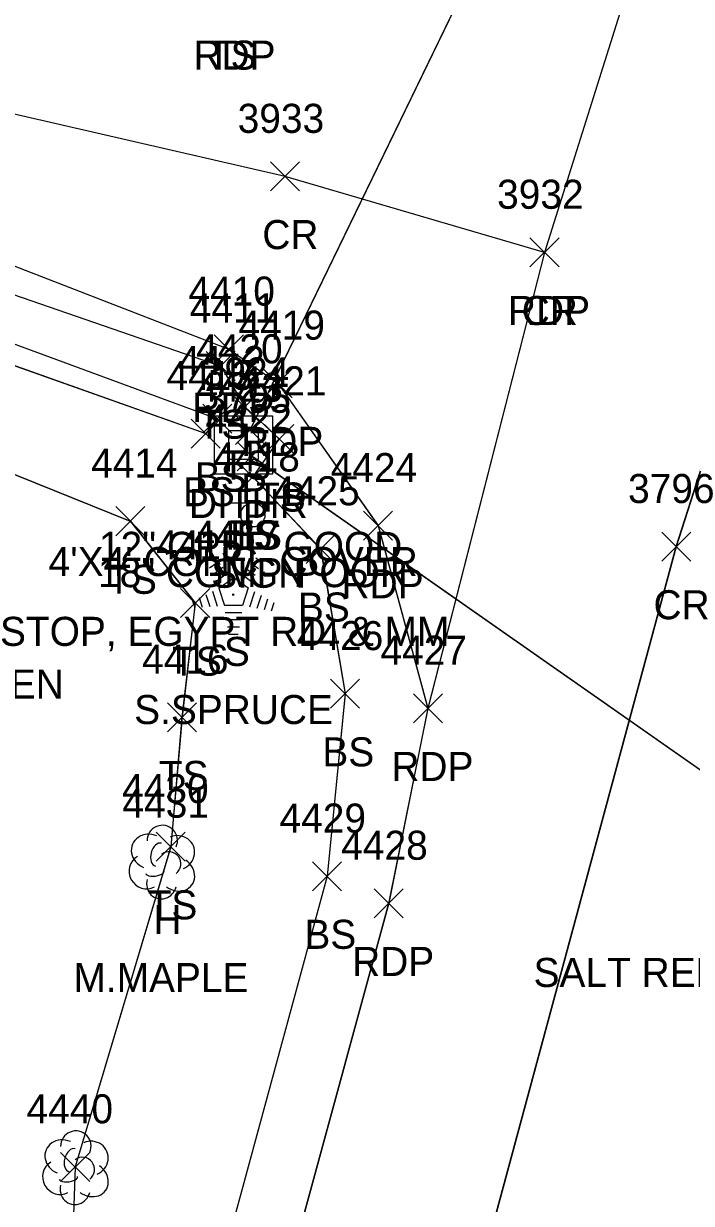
# Model space of a CAD drawing. Extents: x 1554668 to 1563881, y 831386 to 834374.
# Drawn here: x 1562471.8 to 1562517.8, y 833993 to 834074.2 of the extents above; entities that cross this region are included whole.
import ezdxf

# ---------------------------------------------------------------- set-up
doc = ezdxf.new("R2010")
doc.units = 0
for name, color, linetype in [('D_A', 7, 'Continuous'), ('D_C', 7, 'Continuous'), ('D_I', 7, 'Continuous'), ('D_TIC', 7, 'Continuous'), ('DCP', 7, 'Continuous'), ('DS', 7, 'Continuous'), ('L_A', 7, 'Continuous'), ('L_C', 7, 'Continuous'), ('L_I', 7, 'Continuous'), ('L_TIC', 7, 'Continuous'), ('LELB', 7, 'Continuous'), ('LTC', 7, 'Continuous'), ('LTD', 7, 'Continuous'), ('P_A', 7, 'Continuous'), ('P_I', 7, 'Continuous'), ('P_TIC', 7, 'Continuous'), ('PET', 7, 'Continuous'), ('PRC', 7, 'Continuous'), ('S_A', 7, 'Continuous'), ('S_C', 7, 'Continuous'), ('S_I', 7, 'Continuous'), ('SSGN', 7, 'Continuous')]:
    doc.layers.add(name, color=color, linetype=linetype)

msp = doc.modelspace()

# ---------------------------------------------------------------- linework, layer by layer
at = {"layer": 'D_TIC'}
for points in [[(1562486.419, 834045.242), (1562488.419, 834047.242)], [(1562488.419, 834045.242), (1562486.419, 834047.242)], [(1562486.529, 834043.432), (1562488.529, 834045.432)], [(1562488.529, 834043.432), (1562486.529, 834045.432)]]:
    msp.add_lwpolyline(points, dxfattribs=at)
at = {"layer": 'DCP'}
for points in [[(1562487.419, 834046.242), (1562533.892, 834142.054)], [(1562487.423, 834046.249), (1562533.895, 834142.059)], [(1562487.423, 834046.249), (1562533.895, 834142.059)], [(1562487.423, 834046.249), (1562533.895, 834142.059)], [(1562543.528, 834005.24), (1562487.529, 834044.432)], [(1562543.531, 834005.244), (1562487.533, 834044.441)], [(1562543.531, 834005.244), (1562487.533, 834044.441)], [(1562543.531, 834005.244), (1562487.533, 834044.441)]]:
    msp.add_lwpolyline(points, dxfattribs=at)
at = {"layer": 'DS'}
for p, q in [((1562484.96, 834047.215), (1562488.96, 834047.215)), ((1562484.96, 834043.215), (1562484.971, 834047.215)), ((1562488.96, 834047.215), (1562488.96, 834043.215)), ((1562485.96, 834046.215), (1562487.96, 834046.215)), ((1562485.96, 834044.215), (1562485.96, 834046.215)), ((1562487.96, 834046.215), (1562487.96, 834044.215)), ((1562486.963, 834045.225), (1562486.963, 834045.225)), ((1562487.96, 834044.215), (1562485.96, 834044.215)), ((1562488.96, 834043.215), (1562484.96, 834043.215)), ((1562487.46, 834043.215), (1562487.96, 834043.215))]:
    msp.add_line(p, q, dxfattribs=at)
at = {"layer": 'L_TIC'}
for points in [[(1562484.392, 834049.646), (1562486.392, 834051.646)], [(1562486.392, 834049.646), (1562484.392, 834051.646)], [(1562486.046, 834046.838), (1562488.046, 834048.838)], [(1562488.046, 834046.838), (1562486.046, 834048.838)], [(1562484.164, 834046.024), (1562486.164, 834048.024)], [(1562486.164, 834046.024), (1562484.164, 834048.024)], [(1562483.357, 834045), (1562485.357, 834047)], [(1562485.357, 834045), (1562483.357, 834047)], [(1562483.357, 834045), (1562485.357, 834047)], [(1562485.357, 834045), (1562483.357, 834047)], [(1562488.41, 834044.633), (1562490.41, 834046.633)], [(1562490.41, 834044.633), (1562488.41, 834046.633)], [(1562486.603, 834042.022), (1562488.603, 834044.022)], [(1562488.603, 834042.022), (1562486.603, 834044.022)], [(1562486.603, 834042.022), (1562488.603, 834044.022)], [(1562488.603, 834042.022), (1562486.603, 834044.022)], [(1562478.172, 834038.973), (1562480.172, 834040.973)], [(1562480.172, 834038.973), (1562478.172, 834040.973)], [(1562491.263, 834037.064), (1562493.263, 834039.064)], [(1562493.263, 834037.064), (1562491.263, 834039.064)], [(1562482.634, 834033.339), (1562484.634, 834035.339)], [(1562484.634, 834033.339), (1562482.634, 834035.339)], [(1562492.941, 834027.098), (1562494.941, 834029.098)], [(1562494.941, 834027.098), (1562492.941, 834029.098)], [(1562481.728, 834025.474), (1562483.728, 834027.474)], [(1562483.728, 834025.474), (1562481.728, 834027.474)], [(1562480.956, 834016.568), (1562482.956, 834018.568)], [(1562482.956, 834016.568), (1562480.956, 834018.568)], [(1562491.705, 834014.54), (1562493.705, 834016.54)], [(1562493.705, 834014.54), (1562491.705, 834016.54)], [(1562474.382, 833994.53), (1562476.382, 833996.53)], [(1562476.382, 833994.53), (1562474.382, 833996.53)]]:
    msp.add_lwpolyline(points, dxfattribs=at)
at = {"layer": 'LELB'}
for points in [[(1562443.369, 834064.364), (1562440.27, 834060.126), (1562440.179, 834056.769), (1562462.161, 834046.825), (1562479.172, 834039.973), (1562483.634, 834034.339), (1562482.728, 834026.474), (1562481.956, 834017.568), (1562475.382, 833995.53), (1562474.907, 833981.597), (1562477.796, 833971.146), (1562474.671, 833958.863), (1562474.695, 833956.52), (1562476.835, 833955.638), (1562466.528, 833927.959), (1562464.896, 833923.683), (1562456.361, 833893.869), (1562447.843, 833876.92), (1562444.919, 833863.488)], [(1562443.372, 834064.371), (1562440.278, 834060.128), (1562440.185, 834056.774), (1562462.168, 834046.828), (1562479.179, 834039.977), (1562483.64, 834034.343), (1562482.736, 834026.476), (1562481.962, 834017.573), (1562475.384, 833995.54), (1562474.909, 833981.607), (1562477.799, 833971.154), (1562474.676, 833958.869), (1562474.7, 833956.527), (1562476.834, 833955.648), (1562466.529, 833927.967), (1562464.895, 833923.691), (1562456.363, 833893.876), (1562447.847, 833876.928), (1562444.925, 833863.497)], [(1562443.372, 834064.371), (1562440.278, 834060.128), (1562440.185, 834056.774), (1562462.168, 834046.828), (1562479.179, 834039.977), (1562483.64, 834034.343), (1562482.736, 834026.476), (1562481.962, 834017.573), (1562475.384, 833995.54), (1562474.909, 833981.607), (1562477.799, 833971.154), (1562474.676, 833958.869), (1562474.7, 833956.527), (1562476.834, 833955.648), (1562466.529, 833927.967), (1562464.895, 833923.691), (1562456.363, 833893.876), (1562447.847, 833876.928), (1562444.925, 833863.497)], [(1562443.372, 834064.371), (1562440.278, 834060.128), (1562440.185, 834056.774), (1562462.168, 834046.828), (1562479.179, 834039.977), (1562483.64, 834034.343), (1562482.736, 834026.476), (1562481.962, 834017.573), (1562475.384, 833995.54), (1562474.909, 833981.607), (1562477.799, 833971.154), (1562474.676, 833958.869), (1562474.7, 833956.527), (1562476.834, 833955.648), (1562466.529, 833927.967), (1562464.895, 833923.691), (1562456.363, 833893.876), (1562447.847, 833876.928), (1562444.925, 833863.497)], [(1562443.369, 834064.364), (1562466.074, 834057.315), (1562485.392, 834050.646), (1562487.046, 834047.838), (1562489.41, 834045.633), (1562487.603, 834043.022)], [(1562443.372, 834064.371), (1562466.08, 834057.319), (1562485.395, 834050.652), (1562487.05, 834047.844), (1562489.419, 834045.636), (1562487.608, 834043.027)], [(1562443.372, 834064.371), (1562466.08, 834057.319), (1562485.395, 834050.652), (1562487.05, 834047.844), (1562489.419, 834045.636), (1562487.608, 834043.027)], [(1562443.372, 834064.371), (1562466.08, 834057.319), (1562485.395, 834050.652), (1562487.05, 834047.844), (1562489.419, 834045.636), (1562487.608, 834043.027)], [(1562444.493, 834063.001), (1562443.667, 834060.94), (1562464.494, 834053.056), (1562484.357, 834046)], [(1562444.503, 834063.002), (1562443.675, 834060.942), (1562464.497, 834053.062), (1562484.363, 834046.005)], [(1562444.503, 834063.002), (1562443.675, 834060.942), (1562464.497, 834053.062), (1562484.363, 834046.005)], [(1562444.503, 834063.002), (1562443.675, 834060.942), (1562464.497, 834053.062), (1562484.363, 834046.005)], [(1562444.493, 834063.001), (1562464.916, 834054.471), (1562485.164, 834047.024), (1562484.357, 834046)], [(1562444.503, 834063.002), (1562464.924, 834054.474), (1562485.17, 834047.028), (1562484.363, 834046.005)], [(1562444.503, 834063.002), (1562464.924, 834054.474), (1562485.17, 834047.028), (1562484.363, 834046.005)], [(1562444.503, 834063.002), (1562464.924, 834054.474), (1562485.17, 834047.028), (1562484.363, 834046.005)], [(1562487.603, 834043.022), (1562492.263, 834038.064), (1562493.941, 834028.098), (1562492.705, 834015.54), (1562484.92, 833986.839), (1562486.563, 833985.393), (1562478.149, 833957.136), (1562476.214, 833958.05)], [(1562487.608, 834043.027), (1562492.269, 834038.068), (1562493.945, 834028.104), (1562492.707, 834015.549), (1562484.921, 833986.85), (1562486.566, 833985.401), (1562478.156, 833957.142), (1562476.216, 833958.059)], [(1562487.608, 834043.027), (1562492.269, 834038.068), (1562493.945, 834028.104), (1562492.707, 834015.549), (1562484.921, 833986.85), (1562486.566, 833985.401), (1562478.156, 833957.142), (1562476.216, 833958.059)], [(1562487.608, 834043.027), (1562492.269, 834038.068), (1562493.945, 834028.104), (1562492.707, 834015.549), (1562484.921, 833986.85), (1562486.566, 833985.401), (1562478.156, 833957.142), (1562476.216, 833958.059)]]:
    msp.add_lwpolyline(points, dxfattribs=at)
at = {"layer": 'LTC'}
for p, q in [((1562484.419, 834037.218), (1562484.774, 834037.476)), ((1562487.818, 834037.459), (1562488.237, 834037.154)), ((1562484.629, 834036.753), (1562485.158, 834037.137)), ((1562484.838, 834036.287), (1562485.542, 834036.798)), ((1562487.076, 834036.762), (1562487.755, 834036.268)), ((1562487.446, 834037.11), (1562487.996, 834036.711)), ((1562485.048, 834035.821), (1562485.926, 834036.459)), ((1562485.273, 834035.366), (1562486.284, 834036.101)), ((1562486.284, 834036.101), (1562487.281, 834035.376)), ((1562486.704, 834036.414), (1562487.514, 834035.825)), ((1562484.818, 834035.147), (1562485.149, 834034.128)), ((1562485.273, 834035.366), (1562485.66, 834034.173)), ((1562487.281, 834035.376), (1562486.89, 834034.173)), ((1562487.719, 834035.105), (1562487.381, 834034.065)), ((1562483.452, 834034.497), (1562483.604, 834034.03)), ((1562483.907, 834034.714), (1562484.119, 834034.062)), ((1562484.363, 834034.931), (1562484.634, 834034.095)), ((1562486.89, 834034.173), (1562485.66, 834034.173)), ((1562488.163, 834034.855), (1562487.876, 834033.97)), ((1562488.608, 834034.605), (1562488.371, 834033.875)), ((1562489.052, 834034.354), (1562488.866, 834033.78)), ((1562486.852, 834033.673), (1562485.707, 834033.673)), ((1562486.768, 834033.173), (1562485.78, 834033.173)), ((1562486.684, 834032.673), (1562485.853, 834032.673)), ((1562486.601, 834032.173), (1562485.926, 834032.173))]:
    msp.add_line(p, q, dxfattribs=at)
at = {"layer": 'LTD'}
for p, q in [((1562481.326, 834016.562), (1562481.326, 834016.562)), ((1562481.326, 834016.562), (1562481.326, 834016.562)), ((1562475.382, 833995.53), (1562475.382, 833995.53)), ((1562475.382, 833995.53), (1562475.382, 833995.53))]:
    msp.add_line(p, q, dxfattribs=at)
for centre in [(1562481.373, 834017.996), (1562475.429, 833996.964)]:
    msp.add_arc(centre, 1.047, 335.52715, 180.95627, dxfattribs=at)
for centre, major_axis, ratio, start_param, end_param in [((1562480.534, 834017.229), (1.21, -0.512), 0.895232, 1.570796, 4.712389), ((1562482.368, 834017.146), (-1.141, -0.483), 0.949671, 1.570796, 4.712389), ((1562481.118, 834017.021), (-0.208, -0.792), 0.645439, 3.141593, 6.283185), ((1562481.826, 834016.396), (-0.5, 0.667), 0.989748, 3.141593, 6.283185), ((1562480.243, 834015.854), (0.584, -1.042), 0.959034, 3.141593, 6.283185), ((1562482.326, 834015.729), (-1.09, 0.792), 0.841452, 1.570796, 4.712389), ((1562480.868, 834015.812), (-0.625, -0.083), 0.423636, 0, 3.141593), ((1562481.326, 834015.062), (0.265, 1.061), 0.942809, 1.570796, 4.712389), ((1562474.59, 833996.197), (1.21, -0.512), 0.895232, 1.570796, 4.712389), ((1562475.174, 833995.989), (-0.208, -0.792), 0.645439, 3.141593, 6.283185), ((1562476.424, 833996.114), (-1.141, -0.483), 0.949671, 1.570796, 4.712389), ((1562475.882, 833995.364), (-0.5, 0.667), 0.989748, 3.141593, 6.283185), ((1562474.299, 833994.822), (0.584, -1.042), 0.959034, 3.141593, 6.283185), ((1562476.382, 833994.697), (-1.09, 0.792), 0.841452, 1.570796, 4.712389), ((1562474.924, 833994.78), (-0.625, -0.083), 0.423636, 0, 3.141593), ((1562475.382, 833994.03), (0.265, 1.061), 0.942809, 1.570796, 4.712389)]:
    msp.add_ellipse(centre, major_axis=major_axis, ratio=ratio, start_param=start_param, end_param=end_param, dxfattribs=at)
at = {"layer": 'P_TIC'}
for points in [[(1562488.819, 834062.697), (1562490.819, 834064.697)], [(1562490.819, 834062.697), (1562488.819, 834064.697)], [(1562506.663, 834057.473), (1562508.663, 834059.473)], [(1562508.663, 834057.473), (1562506.663, 834059.473)], [(1562506.663, 834057.473), (1562508.663, 834059.473)], [(1562508.663, 834057.473), (1562506.663, 834059.473)], [(1562484.949, 834050.808), (1562486.949, 834052.808)], [(1562486.949, 834050.808), (1562484.949, 834052.808)], [(1562488.315, 834048.467), (1562490.315, 834050.467)], [(1562490.315, 834048.467), (1562488.315, 834050.467)], [(1562495.216, 834038.663), (1562497.216, 834040.663)], [(1562497.216, 834038.663), (1562495.216, 834040.663)], [(1562515.728, 834037.221), (1562517.728, 834039.221)], [(1562517.728, 834037.221), (1562515.728, 834039.221)], [(1562498.641, 834026.091), (1562500.641, 834028.091)], [(1562500.641, 834026.091), (1562498.641, 834028.091)], [(1562498.641, 834026.091), (1562500.641, 834028.091)], [(1562500.641, 834026.091), (1562498.641, 834028.091)], [(1562495.942, 834012.671), (1562497.942, 834014.671)], [(1562497.942, 834012.671), (1562495.942, 834014.671)]]:
    msp.add_lwpolyline(points, dxfattribs=at)
at = {"layer": 'PET'}
for points in [[(1562517.255, 834088.953), (1562507.663, 834058.473), (1562499.641, 834027.091)], [(1562517.258, 834088.963), (1562507.673, 834058.475), (1562499.647, 834027.095)], [(1562517.258, 834088.963), (1562507.673, 834058.475), (1562499.647, 834027.095)], [(1562517.258, 834088.963), (1562507.673, 834058.475), (1562499.647, 834027.095)], [(1562435.459, 834067.179), (1562467.01, 834059.144), (1562485.949, 834051.808), (1562489.315, 834049.467), (1562496.216, 834039.663), (1562499.641, 834027.091), (1562496.942, 834013.671), (1562484.997, 833969.829), (1562474.119, 833928.894), (1562465.329, 833892.835), (1562453.027, 833838.818), (1562446.513, 833813.556), (1562435.697, 833762.843)], [(1562435.465, 834067.183), (1562467.015, 834059.149), (1562485.955, 834051.812), (1562489.324, 834049.47), (1562496.226, 834039.666), (1562499.647, 834027.095), (1562496.946, 834013.679), (1562485.004, 833969.835), (1562474.119, 833928.902), (1562465.328, 833892.841), (1562453.028, 833838.829), (1562446.514, 833813.563), (1562435.7, 833762.854)], [(1562435.465, 834067.183), (1562467.015, 834059.149), (1562485.955, 834051.812), (1562489.324, 834049.47), (1562496.226, 834039.666), (1562499.647, 834027.095), (1562496.946, 834013.679), (1562485.004, 833969.835), (1562474.119, 833928.902), (1562465.328, 833892.841), (1562453.028, 833838.829), (1562446.514, 833813.563), (1562435.7, 833762.854)], [(1562435.465, 834067.183), (1562467.015, 834059.149), (1562485.955, 834051.812), (1562489.324, 834049.47), (1562496.226, 834039.666), (1562499.647, 834027.095), (1562496.946, 834013.679), (1562485.004, 833969.835), (1562474.119, 833928.902), (1562465.328, 833892.841), (1562453.028, 833838.829), (1562446.514, 833813.563), (1562435.7, 833762.854)]]:
    msp.add_lwpolyline(points, dxfattribs=at)
at = {"layer": 'PRC'}
for points in [[(1562507.663, 834058.473), (1562489.819, 834063.697), (1562466.193, 834069.126), (1562436.129, 834075.748), (1562408.218, 834079.724), (1562320.462, 834097.246), (1562291.247, 834107.325), (1562261.719, 834117.67), (1562206.924, 834138.361), (1562180.714, 834150.238), (1562141.773, 834168.724), (1562097.331, 834192.804), (1562041.495, 834228.278), (1562010.592, 834247.192), (1561969.731, 834271.926), (1561947.65, 834288.488), (1561929.769, 834303.06), (1561897.798, 834328.164), (1561868.944, 834345.787)], [(1562507.673, 834058.475), (1562489.821, 834063.703), (1562466.195, 834069.132), (1562436.136, 834075.752), (1562408.228, 834079.731), (1562320.469, 834097.25), (1562291.251, 834107.331), (1562261.726, 834117.669), (1562206.928, 834138.365), (1562180.725, 834150.241), (1562141.776, 834168.728), (1562097.334, 834192.81), (1562041.498, 834228.283), (1562010.595, 834247.198), (1561969.736, 834271.928), (1561947.66, 834288.488), (1561929.776, 834303.061), (1561897.805, 834328.165), (1561868.953, 834345.787)], [(1562507.673, 834058.475), (1562489.821, 834063.703), (1562466.195, 834069.132), (1562436.136, 834075.752), (1562408.228, 834079.731), (1562320.469, 834097.25), (1562291.251, 834107.331), (1562261.726, 834117.669), (1562206.928, 834138.365), (1562180.725, 834150.241), (1562141.776, 834168.728), (1562097.334, 834192.81), (1562041.498, 834228.283), (1562010.595, 834247.198), (1561969.736, 834271.928), (1561947.66, 834288.488), (1561929.776, 834303.061), (1561897.805, 834328.165), (1561868.953, 834345.787)], [(1562507.673, 834058.475), (1562489.821, 834063.703), (1562466.195, 834069.132), (1562436.136, 834075.752), (1562408.228, 834079.731), (1562320.469, 834097.25), (1562291.251, 834107.331), (1562261.726, 834117.669), (1562206.928, 834138.365), (1562180.725, 834150.241), (1562141.776, 834168.728), (1562097.334, 834192.81), (1562041.498, 834228.283), (1562010.595, 834247.198), (1561969.736, 834271.928), (1561947.66, 834288.488), (1561929.776, 834303.061), (1561897.805, 834328.165), (1561868.953, 834345.787)], [(1562374.328, 833358.788), (1562379.819, 833391.645), (1562386.805, 833432.043), (1562394.132, 833473.552), (1562401.52, 833515.146), (1562408.626, 833554.57), (1562418.317, 833607.158), (1562425.122, 833644.153), (1562437.129, 833703.517), (1562446.816, 833750.468), (1562457.117, 833798.654), (1562467.75, 833845.524), (1562476.843, 833883.646), (1562492.325, 833945.243), (1562502.519, 833985.558), (1562516.732, 834038.229), (1562535.447, 834096.625), (1562549.682, 834139.255), (1562553.417, 834150.261)], [(1562374.328, 833358.788), (1562379.819, 833391.645), (1562386.805, 833432.043), (1562394.132, 833473.552), (1562401.52, 833515.146), (1562408.626, 833554.57), (1562418.317, 833607.158), (1562425.122, 833644.153), (1562437.129, 833703.517), (1562446.816, 833750.468), (1562457.117, 833798.654), (1562467.75, 833845.524), (1562476.843, 833883.646), (1562492.325, 833945.243), (1562502.519, 833985.558), (1562516.732, 834038.229), (1562535.447, 834096.625), (1562549.682, 834139.255), (1562553.417, 834150.261)], [(1562374.328, 833358.788), (1562379.819, 833391.645), (1562386.805, 833432.043), (1562394.132, 833473.552), (1562401.52, 833515.146), (1562408.626, 833554.57), (1562418.317, 833607.158), (1562425.122, 833644.153), (1562437.129, 833703.517), (1562446.816, 833750.468), (1562457.117, 833798.654), (1562467.75, 833845.524), (1562476.843, 833883.646), (1562492.325, 833945.243), (1562502.519, 833985.558), (1562516.732, 834038.229), (1562535.447, 834096.625), (1562549.682, 834139.255), (1562553.417, 834150.261)], [(1562374.328, 833358.78), (1562379.82, 833391.635), (1562386.804, 833432.041), (1562394.133, 833473.548), (1562401.522, 833515.144), (1562408.625, 833554.563), (1562418.32, 833607.155), (1562425.125, 833644.147), (1562437.128, 833703.511), (1562446.815, 833750.458), (1562457.117, 833798.648), (1562467.753, 833845.523), (1562476.843, 833883.643), (1562492.321, 833945.235), (1562502.515, 833985.553), (1562516.728, 834038.221), (1562535.444, 834096.612), (1562549.678, 834139.252), (1562553.413, 834150.251)]]:
    msp.add_lwpolyline(points, dxfattribs=at)
at = {"layer": 'SSGN'}
for p, q in [((1562485.953, 834041.243), (1562489.287, 834041.243)), ((1562487.6, 834040.41), (1562487.6, 834040.41))]:
    msp.add_line(p, q, dxfattribs=at)
msp.add_circle((1562487.6, 834040.41), 0.833, dxfattribs=at)

# ---------------------------------------------------------------- texts
at = {"layer": 'D_A'}
for s, p in [('P', (1562486.797, 834041.242)), ('DITHR', (1562483.207, 834040.194)), ('P', (1562486.907, 834039.432))]:
    msp.add_text(s, height=2, dxfattribs=at).set_placement(p)
at = {"layer": 'D_C'}
for s, p in [('12" CPEP GOOD', (1562477.017, 834037.242)), ("4'X4' CONC. COVER", (1562473.553, 834036.194)), ('18" CGMP POOR', (1562476.955, 834035.432))]:
    msp.add_text(s, height=2, dxfattribs=at).set_placement(p)
at = {"layer": 'D_I'}
for s, p in [('3924', (1562484.159, 834049.242)), ('4423', (1562483.719, 834048.194)), ('3795', (1562484.27, 834047.432))]:
    msp.add_text(s, height=2, dxfattribs=at).set_placement(p)
at = {"layer": 'L_A'}
for s, p in [('TS', (1562484.439, 834071.048)), ('TS', (1562483.801, 834045.646)), ('TS', (1562485.456, 834042.838)), ('BS', (1562483.605, 834042.024)), ('BS', (1562482.798, 834041)), ('BS', (1562482.798, 834041)), ('TS', (1562487.819, 834040.633)), ('TS', (1562486.012, 834038.022)), ('BS', (1562486.044, 834038.022)), ('TS', (1562477.581, 834034.973)), ('BS', (1562490.704, 834033.064)), ('S', (1562485.61, 834030.01)), ('TS', (1562482.043, 834029.339)), ('GARDEN', (1562463.155, 834027.765)), ('BS', (1562492.382, 834023.098)), ('TS', (1562481.137, 834021.474)), ('TS', (1562480.366, 834012.568)), ('H', (1562480.759, 834011.562)), ('BS', (1562491.146, 834010.54))]:
    msp.add_text(s, height=2, dxfattribs=at).set_placement(p)
at = {"layer": 'L_C'}
for s, p in [('S.SPRUCE', (1562479.437, 834026.01)), ('M.MAPLE', (1562475.263, 834007.562))]:
    msp.add_text(s, height=2, dxfattribs=at).set_placement(p)
at = {"layer": 'L_I'}
for s, p in [('4411', (1562483.266, 834053.646)), ('4420', (1562483.7, 834050.838)), ('4412', (1562482.471, 834050.024)), ('4413', (1562481.664, 834049)), ('4413', (1562481.664, 834049)), ('4421', (1562486.717, 834048.633)), ('4422', (1562484.343, 834046.022)), ('4422', (1562484.343, 834046.022)), ('4414', (1562476.479, 834042.973)), ('4425', (1562489.003, 834041.064)), ('4417', (1562483.531, 834038.01)), ('4415', (1562480.941, 834037.339)), ('4426', (1562490.626, 834031.098)), ('4416', (1562479.98, 834029.474)), ('4430', (1562478.61, 834020.568)), ('4431', (1562478.633, 834019.562)), ('4429', (1562489.437, 834018.54)), ('4440', (1562472.036, 833998.53)), ('4440', (1562472.036, 833998.53))]:
    msp.add_text(s, height=2, dxfattribs=at).set_placement(p)
at = {"layer": 'LTC'}
msp.add_text('.', height=1.037, rotation=270, dxfattribs=at).set_placement((1562486.167, 834035.114))
at = {"layer": 'P_A'}
for s, p in [('RDP', (1562483.518, 834071.048)), ('CR', (1562488.252, 834058.697)), ('RDP', (1562505.151, 834053.473)), ('CR', (1562506.096, 834053.473)), ('RDP', (1562483.437, 834046.808)), ('RDP', (1562486.803, 834044.467)), ('RDP', (1562493.704, 834034.663)), ('CR', (1562515.161, 834033.221)), ('RDP', (1562497.129, 834022.091)), ('RDP', (1562497.129, 834022.091)), ('RDP', (1562494.431, 834008.671))]:
    msp.add_text(s, height=2, dxfattribs=at).set_placement(p)
at = {"layer": 'P_I'}
for s, p in [('3933', (1562486.559, 834066.697)), ('3932', (1562504.403, 834061.473)), ('3932', (1562504.403, 834061.473)), ('4410', (1562483.169, 834054.808)), ('4419', (1562486.614, 834052.467)), ('4424', (1562492.956, 834042.663)), ('3796', (1562513.413, 834041.221)), ('4427', (1562496.381, 834030.091)), ('4427', (1562496.381, 834030.091)), ('4428', (1562493.683, 834016.671))]:
    msp.add_text(s, height=2, dxfattribs=at).set_placement(p)
at = {"layer": 'S_A'}
msp.add_text('SIGN', height=2, dxfattribs=at).set_placement((1562484.738, 834035.39))
at = {"layer": 'S_C'}
for s, p in [('STOP, EGYPT RD. & MM', (1562470.211, 834031.39)), ('SALT REDUCTION AREA NEXT 9', (1562506.912, 834007.917))]:
    msp.add_text(s, height=2, dxfattribs=at).set_placement(p)
at = {"layer": 'S_I'}
msp.add_text('4418', height=2, dxfattribs=at).set_placement((1562484.888, 834043.39))

doc.saveas('drawing.dxf')
